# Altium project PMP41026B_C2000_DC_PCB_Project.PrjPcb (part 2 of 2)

## Sheet PMP41026B_C2000_DC_LLC_Control.SchDoc
size 558 x 431 mm; Date: Not shown in title block; ApprovedBy: Not shown in title block; CheckedBy: Not shown in title block; Author: Not shown in title block; CompanyName: Not shown in title block; DrawnBy: Desheng Guo; Engineer: Not shown in title block; Organization: Not shown in title block; Address1: Not shown in title block; Address2: Not shown in title block; Address3: Not shown in title block; Address4: Not shown in title block; DocumentNumber: 1; Revision: Use project parameter SCH_Rev; SheetNumber: 4; SheetTotal: 5; PageSetup: Record=PageOptions¦CenterHorizontal=True¦CenterVertical=True¦PrintScale=0.69¦XCorrection=1.00¦YCorrection=1.00¦PrintKind=0¦BorderSize=5000000¦LeftOffset=0¦BottomOffset=0¦Orientation=2¦PaperLength=1000¦PaperWidth=1000¦Scale=100¦PaperSource=15¦PrintQuality=600¦MediaType=1¦DitherType=10¦PaperKind=Letter¦PrintScaleMode=1
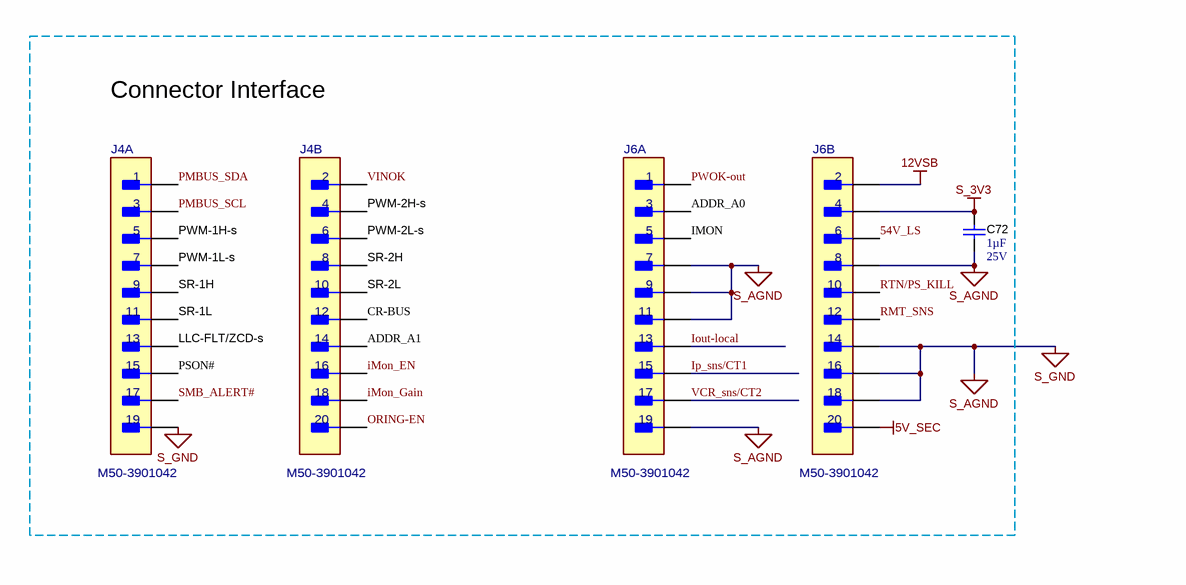
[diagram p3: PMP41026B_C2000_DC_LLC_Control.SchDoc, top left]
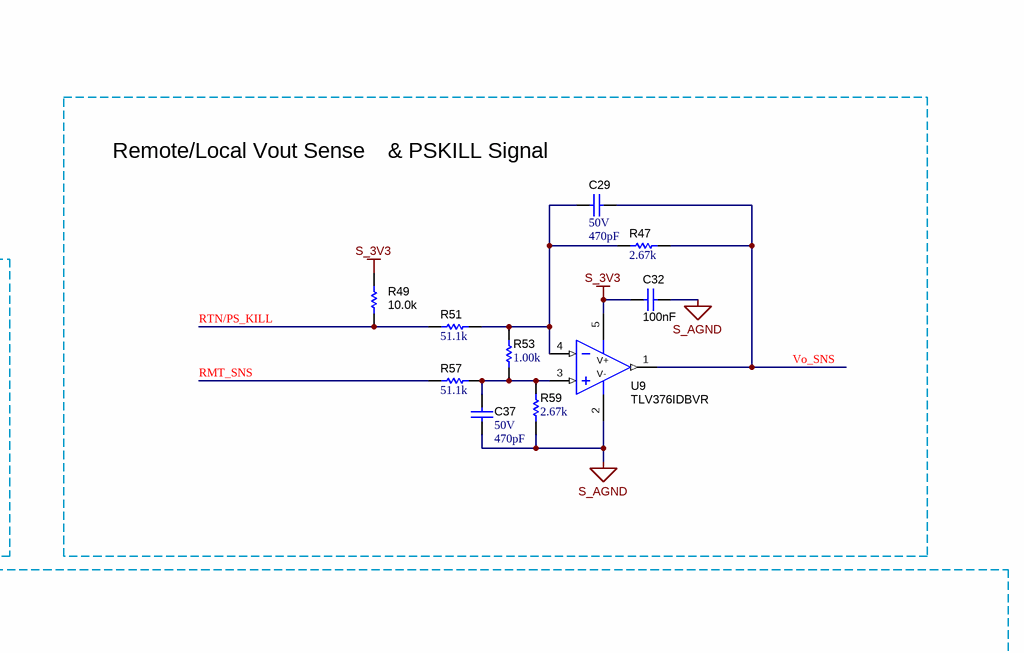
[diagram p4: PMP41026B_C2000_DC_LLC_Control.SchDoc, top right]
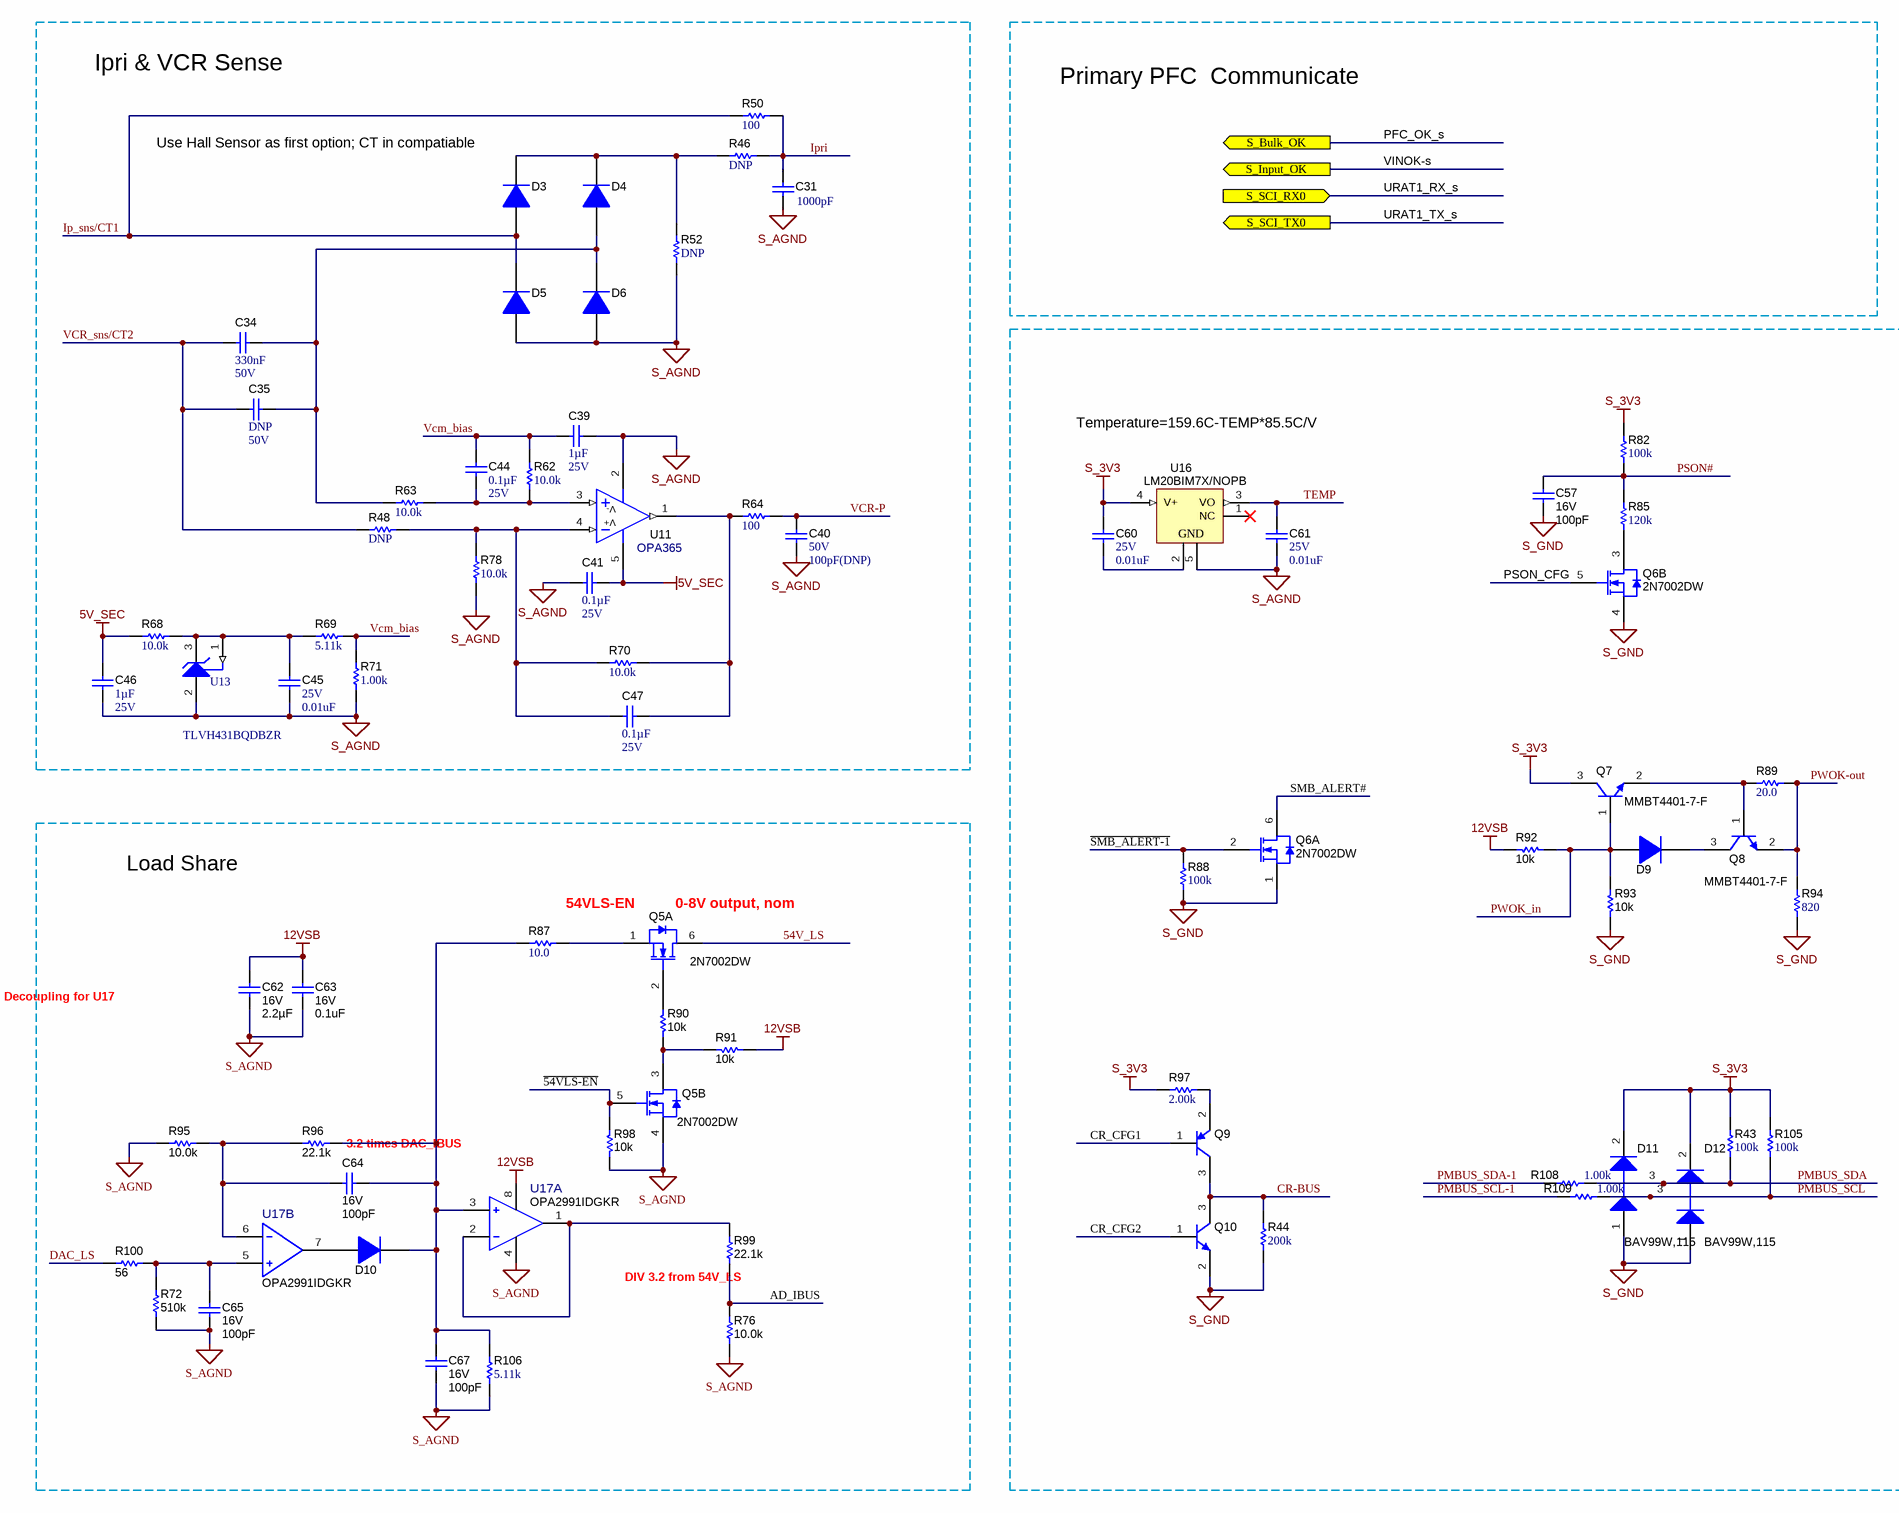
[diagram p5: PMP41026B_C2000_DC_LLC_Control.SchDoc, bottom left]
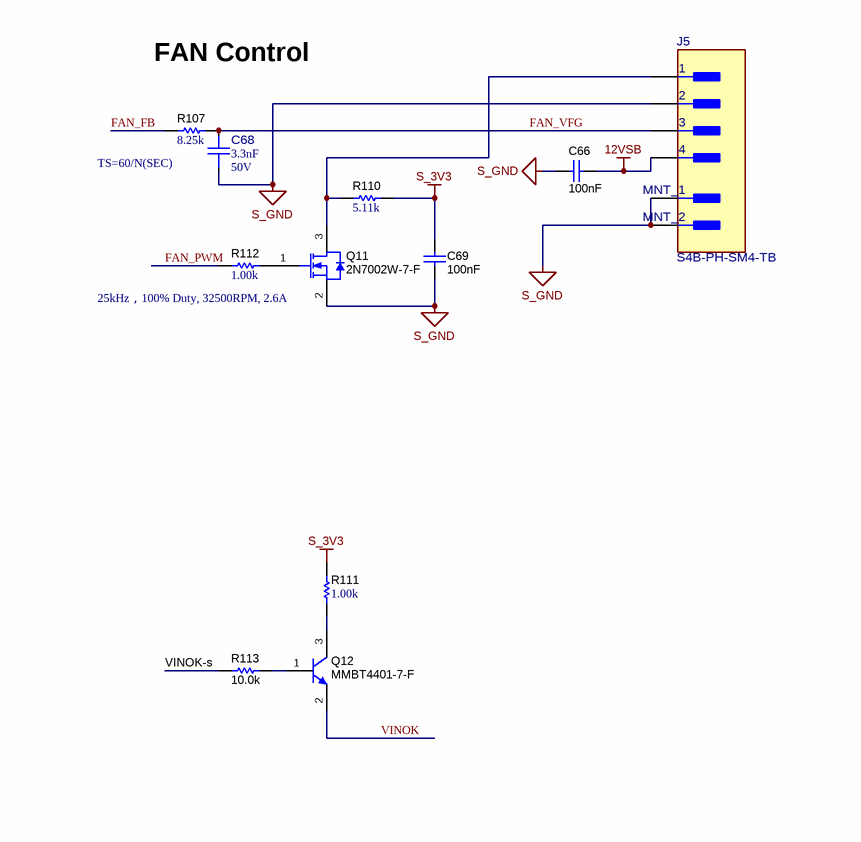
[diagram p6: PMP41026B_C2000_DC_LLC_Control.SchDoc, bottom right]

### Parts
C29  VDC_V: 50V  ValueDisplayed: 470pF  [0402]  (hidden comment: GRM155R71H471KA01D)
C31  ValueDisplayed: 1000pF  [0402]  (hidden comment: GRM155R72A102KA01D)
C32  Cap_F: 100nF  [0603]  (hidden comment: GRM188R71E104KA01D)
C34  Cap_F: 330nF  VDC_V: 50V  [0603]  (hidden comment: C1608X7R1H334K080AC)
C35  Cap_F: DNP  VDC_V: 50V  [0603]  (hidden comment: C1608X7R1H334K080AC)  (no BOM)
C37  VDC_V: 50V  ValueDisplayed: 470pF  [0402]  (hidden comment: GRM155R71H471KA01D)
C39  Cap_F: 1µF  VDC_V: 25V  [0603]  (hidden comment: 885012206076)
C40  VDC_V: 50V  ValueDisplayed: 100pF(DNP)  [0402]  (hidden comment: CC0402KRX7R9BB101)  (no BOM)
C41  ValueDisplayed: 0.1µF  VDC_V: 25V  [0402]  (hidden comment: CC0402KRX7R8BB104)
C44  ValueDisplayed: 0.1µF  VDC_V: 25V  [0402]  (hidden comment: CC0402KRX7R8BB104)
C45  VDC_V: 25V  ValueDisplayed: 0.01uF  [0402]  (hidden comment: GRM155R71E103KA01D)
C46  Cap_F: 1µF  VDC_V: 25V  [0603]  (hidden comment: 885012206076)
C47  ValueDisplayed: 0.1µF  VDC_V: 25V  [0402]  (hidden comment: CC0402KRX7R8BB104)
C57  VDC_V: 16V  ValueDisplayed: 100pF  [0402]  (hidden comment: 0402YC101KAT2A)
C60  VDC_V: 25V  ValueDisplayed: 0.01uF  [0402]  (hidden comment: GCM155R71E103KA37D)
C61  VDC_V: 25V  ValueDisplayed: 0.01uF  [0402]  (hidden comment: GCM155R71E103KA37D)
C62  VDC_V: 16V  Cap_F: 2.2µF  [0603]  (hidden comment: GRM188Z71C225KE43)
C63  VDC_V: 16V  ValueDisplayed: 0.1uF  [0402]  (hidden comment: GRM155R71C104KA88D)
C64  VDC_V: 16V  ValueDisplayed: 100pF  [0402]  (hidden comment: 0402YC101KAT2A)
C65  VDC_V: 16V  ValueDisplayed: 100pF  [0402]  (hidden comment: 0402YC101KAT2A)
C66  Cap_F: 100nF  [0603]  (hidden comment: GRM188R71E104KA01D)
C67  VDC_V: 16V  ValueDisplayed: 100pF  [0402]  (hidden comment: 0402YC101KAT2A)
C68  ValueDisplayed: 3.3nF  VDC_V: 50V  [FP-885012205064_0402-MFG]  (hidden comment: 885012205064)
C69  Cap_F: 100nF  [0603]  (hidden comment: GRM188R71E104KA01D)
C72  Cap_F: 1µF  VDC_V: 25V  [0603]  (hidden comment: 885012206076)
D3  BAS316,115  [SOD-323]  (value not drawn)
D4  BAS316,115  [SOD-323]  (value not drawn)
D5  BAS316,115  [SOD-323]  (value not drawn)
D6  BAS316,115  [SOD-323]  (value not drawn)
D9  BAS516,115  [SOD-523]  (value not drawn)
D10  BAS516,115  [SOD-523]  (value not drawn)
D11  BAV99W,115  [SOT-323]
D12  BAV99W,115  [SOT-323]
J4  M50-3901042  [FP-M50-3901042_HDR20-MFG]  (parts A,B of 2)
J5  S4B-PH-SM4-TB  [FP-S4B-PH-SM4-TB_CONN_HDR4-MFG]
J6  M50-3901042  [FP-M50-3901042_HDR20-MFG]  (parts A,B of 2)
Q5  2N7002DW  [SOT-363]  (parts A,B of 2)
Q6  2N7002DW  [SOT-363]  (parts A,B of 2)
Q7  MMBT4401-7-F  [SOT-23]
Q8  MMBT4401-7-F  [SOT-23]
Q9  MMBT4403  [SOT-23]  (value not drawn)
Q10  MMBT4401-7-F  [SOT-23]  (value not drawn)
Q11  2N7002W-7-F  [SOT-323]
Q12  MMBT4401-7-F  [SOT-23]
R43  ValueDisplayed: 100k  [0402]  (hidden comment: RC1005F104CS)
R44  ValueDisplayed: 200k  [0402]  (hidden comment: ERJ-2RKF2003X)
R46  ValueDisplayed: DNP  [0402]  (hidden comment: RC0402FR-07100RL)  (no BOM)
R47  ValueDisplayed: 2.67k  [0402]  (hidden comment: CRCW04022K67FKED)
R48  ValueDisplayed: DNP  [0402]  (hidden comment: CRCW040210K0FKED)  (no BOM)
R49  ValueDisplayed: 10.0k  [0402]  (hidden comment: CRCW040210K0FKED)
R50  ValueDisplayed: 100  [0402]  (hidden comment: RC0402FR-07100RL)
R51  ValueDisplayed: 51.1k  [0402]  (hidden comment: CRCW040251K1FKED)
R52  ValueDisplayed: DNP  [0805_HV]  (hidden comment: RC0805JR-072R2L)  (no BOM)
R53  ValueDisplayed: 1.00k  [0402]  (hidden comment: ERJ-2RKF1001X)
R57  ValueDisplayed: 51.1k  [0402]  (hidden comment: CRCW040251K1FKED)
R59  ValueDisplayed: 2.67k  [0402]  (hidden comment: CRCW04022K67FKED)
R62  ValueDisplayed: 10.0k  [0402]  (hidden comment: CRCW040210K0FKED)
R63  ValueDisplayed: 10.0k  [0402]  (hidden comment: CRCW040210K0FKED)
R64  ValueDisplayed: 100  [0402]  (hidden comment: RC0402FR-07100RL)
R68  ValueDisplayed: 10.0k  [0402]  (hidden comment: CRCW040210K0FKED)
R69  ValueDisplayed: 5.11k  [0402]  (hidden comment: CRCW04025K11FKED)
R70  ValueDisplayed: 10.0k  [0402]  (hidden comment: CRCW040210K0FKED)
R71  ValueDisplayed: 1.00k  [0402]  (hidden comment: RC0402FR-071KL)
R72  ValueDisplayed: 510k  [0402]  (hidden comment: CRCW0402510KJNED)
R76  ValueDisplayed: 10.0k  [0402]  (hidden comment: CRCW040210K0FKED)
R78  ValueDisplayed: 10.0k  [0402]  (hidden comment: CRCW040210K0FKED)
R82  ValueDisplayed: 100k  [0402]  (hidden comment: RC1005F104CS)
R85  ValueDisplayed: 120k  [0402]  (hidden comment: ERJ-2RKF1203X)
R87  ValueDisplayed: 10.0  [0402]  (hidden comment: MCR01MZPF10R0)
R88  ValueDisplayed: 100k  [0402]  (hidden comment: RC1005F104CS)
R89  ValueDisplayed: 20.0  [0402]  (hidden comment: CRCW040220R0FKED)
R90  ValueDisplayed: 10k  [0402]  (hidden comment: CRCW040210K0JNED)
R91  ValueDisplayed: 10k  [0402]  (hidden comment: CRCW040210K0JNED)
R92  ValueDisplayed: 10k  [0402]  (hidden comment: CRCW040210K0JNED)
R93  ValueDisplayed: 10k  [0402]  (hidden comment: CRCW040210K0JNED)
R94  ValueDisplayed: 820  [0402]  (hidden comment: RC0402FR-07820RL)
R95  ValueDisplayed: 10.0k  [0402]  (hidden comment: CRCW040210K0FKED)
R96  ValueDisplayed: 22.1k  [0402]  (hidden comment: CRCW040222K1FKED)
R97  ValueDisplayed: 2.00k  [0402]  (hidden comment: CRCW04022K00FKED)
R98  ValueDisplayed: 10k  [0402]  (hidden comment: CRCW040210K0JNED)
R99  ValueDisplayed: 22.1k  [0402]  (hidden comment: CRCW040222K1FKED)
R100  ValueDisplayed: 56  [0402]  (hidden comment: CRCW040256R0JNED)
R105  ValueDisplayed: 100k  [0402]  (hidden comment: RC1005F104CS)
R106  ValueDisplayed: 5.11k  [0402]  (hidden comment: CRCW04025K11FKED)
R107  ValueDisplayed: 8.25k  [0402]  (hidden comment: CRCW04028K25FKED)
R108  ValueDisplayed: 1.00k  [0402]  (hidden comment: ERJ-2RKF1001X)
R109  ValueDisplayed: 1.00k  [0402]  (hidden comment: ERJ-2RKF1001X)
R110  ValueDisplayed: 5.11k  [0402]  (hidden comment: CRCW04025K11FKED)
R111  ValueDisplayed: 1.00k  [0402]  (hidden comment: RC0402FR-071KL)
R112  ValueDisplayed: 1.00k  [0402]  (hidden comment: ERJ-2RKF1001X)
R113  ValueDisplayed: 10.0k  [0402]  (hidden comment: CRCW040210K0FKED)
U9  TLV376IDBVR  [DBV0005A_N]
U11  OPA365  [DBV0005A_N]
U13  TLVH431BQDBZR  [DBZ0003A_N]
U16  LM20BIM7X/NOPB  [DCK0005A_N]
U17  OPA2991IDGKR  [DGK0008A-MFG]  (parts A,B of 2)

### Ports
S_Bulk_OK (out), S_Input_OK (out), S_SCI_RX0 (in), S_SCI_TX0 (out)

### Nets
5V_SEC: C41.1 C46.2 J6.20 R68.1 U11.5(V+)
12VSB: C62.1 C63.1 C66.1 J5.4 J6.2 R91.2 R92.1 U17.8(v+)
S_3V3: C32.2 C60.1 C69.2 C72.2 D11.2(K) D12.2(K) J6.4 Q7.3(C) R43.2 R49.1 R82.2 R97.2 R105.2 R110.1 R111.2 U9.5(V+) U16.4(V+)
S_AGND: C31.2 C32.1 C37.2 C39.2 C40.2 C41.2 C45.2 C46.1 C57.2 C61.2 C62.2 C63.2 C65.2 C66.2 C67.2 C68.1 C69.1 C72.1 D5.2(A) D6.2(A) D11.1(A) D12.1(A) J4.19 J5.2 J5.5(MNT_1) J5.6(MNT_2) J6.7 J6.8 J6.9 J6.11 J6.14 J6.16 J6.18 J6.19 Q5.4(S) Q6.1(S) Q6.4(S) Q10.2(E) Q11.2(S) R44.1 R52.1 R59.1 R71.1 R72.1 R76.1 R78.1 R88.1 R93.1 R94.1 R95.2 R98.2 R106.1 U9.2(V-) U11.2(V-) U13.2(CATHODE) U16.5(GND) U17.4(V-)  [also labelled S_GND]
54V_LS: J6.6 Q5.6(D)
~{54VLS-EN}: Q5.5(G) R98.1
~{SMB_ALERT-1}: Q6.2(G) R88.2
AD_IBUS: R76.2 R99.1
ADDR_A0: J6.3
ADDR_A1: J4.14
CR-BUS: J4.12 Q9.3(C) Q10.3(C) R44.2
CR_CFG1: Q9.1(B)
CR_CFG2: Q10.1(B)
DAC_LS: R100.1
FAN_FB: R107.1
FAN_PWM: R112.2
FAN_VFG: C68.2 J5.3 R107.2
IMON: J6.5
iMon_EN: J4.16
iMon_Gain: J4.18
Iout-local: J6.13
Ip_sns/CT1: D3.2(A) D5.1(K) J6.15 R50.1
Ipri: C31.1 R46.2 R50.2
LLC-FLT/ZCD-s: J4.13
ORING-EN: J4.20
PMBUS_SCL: D12.3(C) J4.3 R105.1 R109.2
PMBUS_SCL-1: R109.1  [project net MCU_GPIO24]
PMBUS_SDA: D11.3(C) J4.1 R43.1 R108.2
PMBUS_SDA-1: R108.1
PSON#: C57.1 J4.15 R82.1 R85.2
PSON_CFG: Q6.5(G)
PWM-1H-s: J4.5
PWM-1L-s: J4.7
PWM-2H-s: J4.4
PWM-2L-s: J4.6
PWOK-out: J6.1 Q8.2(E) R89.2 R94.2
PWOK_in: D9.2(A) Q7.1(B) R92.2 R93.2
RMT_SNS: J6.12 R57.1
RTN/PS_KILL: J6.10 R49.2 R51.1
SMB_ALERT#: J4.17 Q6.6(D)
SR-1H: J4.9
SR-1L: J4.11
SR-2H: J4.8
SR-2L: J4.10
TEMP: C61.1 U16.3(VO)
Vcm_bias: C39.1 C44.1 R62.2 R69.1 R71.2
VCR-P: C40.1 R64.2
VCR_sns/CT2: C34.2 C35.2 J6.17 R48.1
VINOK: J4.2 Q12.2(E)
VINOK-s: R113.1 ; port S_Input_OK
Vo_SNS: C29.2 R47.2 U9.1(OUT)
NetC29_1: C29.1 R47.1 R51.2 R53.2 U9.4(IN-)
NetC34_1: C34.1 C35.1 D4.2(A) D6.1(K) R63.1
NetC37_1: C37.1 R53.1 R57.2 R59.2 U9.3(IN+)
NetC44_2: C44.2 R62.1 R63.2 U11.3(IN+)
NetC45_1: C45.1 R68.2 R69.2 U13.1(REF) U13.3(ANODE)
NetC47_1: C47.1 R64.1 R70.2 U11.1(OUT)
NetC47_2: C47.2 R48.2 R70.1 R78.2 U11.4(IN-)
NetC60_2: C60.2 U16.2(GND)
NetC64_1: C64.1 R95.1 R96.1 U17.6(IN2-)
NetC64_2: C64.2 C67.1 D10.1(K) R87.1 R96.2 R106.2 U17.3(IN1+)
NetC65_1: C65.1 R72.2 R100.2 U17.5(IN2+)
NetD3_1: D3.1(K) D4.1(K) R46.1 R52.2
NetD9_1: D9.1(K) Q8.3(C)
NetD10_2: D10.2(A) U17.7(OUT2)
NetJ5_1: J5.1 Q11.3(D) R110.2
NetQ5_1: Q5.1(S) R87.2
NetQ5_2: Q5.2(G) R90.1
NetQ5_3: Q5.3(D) R90.2 R91.1
NetQ6_3: Q6.3(D) R85.1
NetQ7_2: Q7.2(E) Q8.1(B) R89.1
NetQ9_2: Q9.2(E) R97.1
NetQ11_1: Q11.1(G) R112.1
NetQ12_1: Q12.1(B) R113.2
NetQ12_3: Q12.3(C) R111.1
NetR99_2: R99.2 U17.1(OUT1) U17.2(IN1-)

Not connected (* = marked no-connect by the designer): U16 1(NC)*

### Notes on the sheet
- Connector Interface
- Remote/Local Vout Sense
- & PSKILL Signal
- Ipri & VCR Sense
- Primary PFC  Communicate
- (near D3) Use Hall Sensor as first option; CT in compatiable
- Temperature=159.6C-TEMP*85.5C/V
- FAN Control
- (near R107) TS=60/N(SEC)
- 25kHz，100% Duty, 32500RPM, 2.6A
- Load Share
- (near Q5) 54VLS-EN
- 0-8V output, nom
- (near C62) Decoupling for U17
- 3.2 times DAC_IBUS
- (near R99) DIV 3.2 from 54V_LS

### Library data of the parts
C29 C37 = CMP-0006691-2: CAP, CERM, 470 pF, 50 V, +/- 10%, X7R, 0402; Manufacturer: MuRata; TaMin_C: -55°C; Polarized: N; SizeAreaWB_mm2: 3; Value1: Unknown; U/M: EA; Value: 470pF; TaMax_C: 125°C; SizeZ_mm: 0.6; SizeX_mm: 1; SizeY_mm: 0.5; AEC Category: Q200
C31 = CMP-0006699-2: CAP, CERM, 1000 pF, 100 V, +/- 10%, X7R, 0402; Manufacturer: MuRata; TaMin_C: -55°C; Polarized: N; SizeAreaWB_mm2: 3; Value1: Unknown; U/M: EA; Value: 1000pF; TaMax_C: 125°C; SizeZ_mm: 0.6; SizeX_mm: 1; SizeY_mm: 0.5; Value2: 100V; Cap_F: 1nF; AEC Category: Q200
C32 C66 C69 = CMP-0007404-4: CAP, CERM, 0.1 uF, 25 V, +/- 10%, X7R, 0603; Manufacturer: MuRata; TaMin_C: -55°C; Polarized: N; SizeAreaWB_mm2: 4.68; Value1: Unknown; U/M: EA; Value: 0.1uF; TaMax_C: 125°C; SizeZ_mm: 1; SizeX_mm: 1.6; SizeY_mm: 0.8; Value2: 25V; SizeArea_mm2: 1.28; CompType: Capacitor; AEC Category: Q200
C34 C35 = CMP-0007048-4: CAP, CERM, 0.33 uF, 50 V, +/- 10%, X7R, 0603; Manufacturer: TDK; TaMin_C: -55°C; ESR_ohm: 0.016574; Polarized: N; SizeAreaWB_mm2: 4.68; Value1: 0.016574 ohm; U/M: EA; Value: 0.33uF; TaMax_C: 125°C; SizeZ_mm: 1; SizeX_mm: 1.6; SizeY_mm: 0.8; SizeArea_mm2: 1.28; IRMS_A: 1.28367A; AEC Category: Q200
C39 C46 C72 = CMP-0006833-4: CAP, CERM, 1 uF, 25 V, +/- 10%, X7R, 0603; Manufacturer: Wurth Elektronik; TaMin_C: -55°C; Polarized: N; SizeAreaWB_mm2: 4.68; Value1: Unknown; U/M: EA; Value: 1uF; TaMax_C: 125°C; SizeZ_mm: 1; SizeX_mm: 1.6; SizeY_mm: 0.8; SizeArea_mm2: 1.28; AEC Category: Q200
C40 = CMP-0006305-2: CAP, CERM, 100 pF, 50 V, +/- 10%, X7R, 0402; Manufacturer: Yageo America; TaMin_C: -55°C; Polarized: N; SizeAreaWB_mm2: 3; Value1: Unknown; U/M: EA; Value: 100pF; TaMax_C: 125°C; SizeZ_mm: 0.6; SizeX_mm: 1; SizeY_mm: 0.5; AEC Category: Q200
C41 C44 C47 = CMP-0860555-1: CAP, CERM, 0.1 µF, 25 V,+/- 10%, X7R, 0402; Manufacturer: Yageo; SizeArea_mm2: 0.5; AEC Qualified: N; SizeX_mm: 1; U/M: EA; Value: 0.1uF; TaMin_C: -55°C; SizeZ_mm: 0.6; Cap_F: 100nF; TaMax_C: 125°C; SizeAreaWB_mm2: 3; AEC Category: Q200
C45 = CMP-0006658-2: CAP, CERM, 0.01 uF, 25 V, +/- 10%, X7R, 0402; Manufacturer: MuRata; TaMin_C: -55°C; Polarized: N; SizeAreaWB_mm2: 3; Value1: Unknown; U/M: EA; Value: 0.01uF; TaMax_C: 125°C; SizeZ_mm: 0.6; SizeX_mm: 1; SizeY_mm: 0.5; Cap_F: 10nF; AEC Category: Q200
C57 C64 C65 C67 = CMP-0006200-2: CAP, CERM, 100 pF, 16 V, +/- 10%, X7R, 0402; Manufacturer: AVX; TaMin_C: -55°C; Polarized: N; SizeAreaWB_mm2: 3; Value1: Unknown; U/M: EA; Value: 100pF; TaMax_C: 125°C; SizeZ_mm: 0.6; SizeX_mm: 1; SizeY_mm: 0.5; AEC Category: Q200
C60 C61 = CMP-0006352-2: CAP, CERM, 0.01 uF, 25 V, +/- 10%, X7R, 0402; Manufacturer: MuRata; TaMin_C: -55°C; Polarized: N; SizeAreaWB_mm2: 3; Value1: Unknown; U/M: EA; Value: 0.01uF; TaMax_C: 125°C; SizeZ_mm: 0.6; SizeX_mm: 1; SizeY_mm: 0.5; Cap_F: 10nF; AEC Category: Q200
C62 = CMP-0007499-4: CAP, CERM, 2.2 uF, 16 V, +/- 10%, X7R, 0603; Manufacturer: MuRata; TaMin_C: -55°C; Polarized: N; SizeAreaWB_mm2: 4.68; Value1: Unknown; U/M: EA; Value: 2.2uF; TaMax_C: 125°C; SizeZ_mm: 1; SizeX_mm: 1.6; SizeY_mm: 0.8; SizeArea_mm2: 1.28; AEC Category: Q200
C63 = CMP-0006641-2: CAP, CERM, 0.1 uF, 16 V, +/- 10%, X7R, 0402; Manufacturer: MuRata; TaMin_C: -55°C; Polarized: N; SizeAreaWB_mm2: 3; Value1: Unknown; U/M: EA; Value: 0.1uF; TaMax_C: 125°C; SizeZ_mm: 0.6; SizeX_mm: 1; SizeY_mm: 0.5; Cap_F: 100nF; AEC Category: Q200
C68 = CMP-0092424-1: Cap Cer 3300pF 50V X7R 0402; Manufacturer: Wurth Electronics; TempCo: 15%; AEC Qualified: No; Value: 3.3nF; SizeZ_mm: 0.55mm; Tolerance_%: 10%
D3-D6 = CMP-0029006-1: Diode, Ultrafast, 100 V, 0.25 A, SOD-323; Manufacturer: Nexperia; Io_A: 250mA; Green_Lifecycle: Not Set; SizeAreaWB_mm2: 8.695; Vr_V: 100V; Green_REACh: Incomplete; Value1: 0.25A; TJmax_C: 150°C; U/M: EA; Value: 100V; SizeZ_mm: 1; SizeX_mm: 2.7; SizeY_mm: 1.35; Vf_V: 1.4V; SizeArea_mm2: 3.645; AEC Category: Q101
D9 D10 = CMP-0076979-3: Diode, Switching, 100 V, 0.25 A, SOD-523; Manufacturer: Nexperia; Value: 100V; SizeAreaWB_mm2: 5.13; Vf_V: 1.25V; SizeArea_mm2: 1.53; SizeY_mm: 0.9; Green_Lifecycle: Not Set; AEC Category: Q101; SizeX_mm: 1.7; Green_REACh: Incomplete; Io_A: 250mA; TJmax_C: 150°C; SizeZ_mm: 0.65; Value1: 0.25A
D11 D12 = CMP-0076926-2: Diode, Switching, 100 V, 0.15 A, SOT-323; Manufacturer: Nexperia; AEC Category: Q101; SizeAreaWB_mm2: 10.24; TJmax_C: 150°C; Green_REACh: Incomplete; SizeArea_mm2: 4.84; Value: 100V; Vf_V: 1.25V; Green_Lifecycle: Not Set; SizeZ_mm: 1.1; Value1: 0.15A; Io_A: 150mA; SizeY_mm: 2.2
J4 J6 = CMP-0122579-1: Connector Header Through Hole, Right Angle 20 position 0.050" (1.27mm); Manufacturer: Harwin; ContactFinish: Gold,Nickel; Current_A: 1A; Row_Count: 2; AEC Qualified: No; Conn Gender: Male; Conn Orientation: Horizontal; SizeZ_mm: 3.55mm
J5 = CMP-0123064-1: Connector Header, PH Series, 4 Position, Side Entry, 2.00mm, Solder, Surface Mount, Natural.; Manufacturer: JST; ContactFinish: Tin,Copper; Current_A: 2A; Row_Count: 1; Voltage_V: 100V; AEC Qualified: No; DUT-Pitch_mm: 2mm; SizeZ_mm: 5.5mm
Q5 Q6 = CMP-0000770-1: MOSFET, 2-CH, N-CH, 60 V, 0.115 A, SOT-363; Alternate Manufacturer: None; Manufacturer: Fairchild Semiconductor; SizeZ_mm: 1.1; ChType: N; VdsMax_V: 60V; SizeX_mm: 2.2; Vgs_V: 20V; Value: 60V; SizeArea_mm2: 4.84; AEC Category: Q101; IdsMax_A: 1.15dA; SizeAreaWB_mm2: 10.24; U/M: EA
Q7 Q8 Q10 Q12 = CMP-0000388-2: Transistor, NPN, 40 V, 0.15 A, SOT-23; Manufacturer: Diodes Inc.; TaMax_C: 150°C; Value2: 300; Value1: 0.15 A; Vcesat1_V: 4dV; SizeX_mm: 2.5; SizeY_mm: 3; TaMin_C: -55°C; IcRated_A: 1.5dA; CompType: BJT; SizeZ_mm: 1.1; Value: 40 V; SizeArea_mm2: 7.5; NPN: 1; Vceo_V: 40V; PNP: 0; AEC Category: Q101; SizeAreaWB_mm2: 14; U/M: EA
Q9 = CMP-0000327-2: Transistor, PNP, 40 V, 0.6 A, SOT-23; Manufacturer: Fairchild Semiconductor; TaMax_C: 150°C; Value2: 500; Value1: 0.6 A; Vcesat1_V: 7.5dV; SizeX_mm: 2.5; SizeY_mm: 3; TaMin_C: -55°C; IcRated_A: 6dA; CompType: BJT; SizeZ_mm: 1.1; Value: 40 V; SizeArea_mm2: 7.5; NPN: 0; Vceo_V: 40V; PNP: 1; AEC Category: Q101; SizeAreaWB_mm2: 14; U/M: EA
Q11 = CMP-0000776-1: MOSFET, N-CH, 60 V, 0.115 A, SOT-323; Alternate Manufacturer: None; Manufacturer: Diodes Inc.; SizeZ_mm: 1.1; ChType: N; Value1: 7; VdsMax_V: 60V; SizeX_mm: 2.2; Vgs_V: 20V; Value: 60V; Rdson45_ohm: 7.5; SizeArea_mm2: 4.84; AEC Category: Q101; IdsMax_A: 1.15dA; SizeAreaWB_mm2: 10.24; U/M: EA
R43 R82 R88 R105 = CMP-0026745-1: RES, 100 k, 1%, 0.063 W, 0402; Manufacturer: Samsung Electro-Mechanics; Power_W: 63mW; TempCo: 100 ppm/C; U/M: EA; Value: 100k; EIA_Code: E96; SizeX_mm: 1; SizeY_mm: 0.5; SizeZ_mm: 0.6; Value2: 0.063W; AEC Qualified: N; VDC_V: 80V; AEC Category: Q200
R44 = CMP-0026677-1: RES, 200 k, 1%, 0.1 W, 0402; Manufacturer: Panasonic; Power_W: 100mW; TempCo: 100 ppm/C; U/M: EA; Value: 200k; EIA_Code: E96; SizeX_mm: 1; SizeY_mm: 0.5; SizeZ_mm: 0.6; Value2: 0.1W; VDC_V: 50V; AEC Category: Q200
R46 R50 R64 = CMP-0026722-1: RES, 100, 1%, 0.063 W, 0402; Manufacturer: Yageo America; Power_W: 63mW; TempCo: 100 ppm/C; Value_Code: 100R; U/M: EA; Value: 100; EIA_Code: E96; SizeX_mm: 1; SizeY_mm: 0.5; SizeZ_mm: 0.6; Value2: 0.063W; AEC Qualified: N; VDC_V: 50V; AEC Category: Q200
R47 R59 = CMP-0026240-2: RES, 2.67 k, 1%, 0.063 W, AEC-Q200 Grade 0, 0402; Manufacturer: Vishay-Dale; Power_W: 63mW; TempCo: 100 ppm/C; Value_Code: 2k67; Value: 2.67k; EIA_Code: E96; SizeX_mm: 1; SizeY_mm: 0.5; SizeZ_mm: 0.6; Value2: 0.063W; AEC Qualified: Y; VDC_V: 50V; AEC Category: Q200; AEC Grade: 0
R48 R49 R62 R63 R68 R70 R76 R78 R95 R113 = CMP-0025958-3: RES, 10.0 k, 1%, 0.063 W, AEC-Q200 Grade 0, 0402; Manufacturer: Vishay-Dale; Power_W: 63mW; TempCo: 100 ppm/C; Value_Code: 10k0; Value: 10.0k; EIA_Code: E96; Res_ohm: 10k; SizeX_mm: 1; SizeY_mm: 0.5; SizeZ_mm: 0.6; Value2: 0.063W; AEC Qualified: Y; VDC_V: 50V; AEC Category: Q200; AEC Grade: 0
R51 R57 = CMP-0026437-2: RES, 51.1 k, 1%, 0.063 W, AEC-Q200 Grade 0, 0402; Manufacturer: Vishay-Dale; Power_W: 63mW; TempCo: 100 ppm/C; Value_Code: 51k1; Value: 51.1k; EIA_Code: E96; SizeX_mm: 1; SizeY_mm: 0.5; SizeZ_mm: 0.6; Value2: 0.063W; AEC Qualified: Y; VDC_V: 50V; AEC Category: Q200; AEC Grade: 0
R52 = CMP-0020812-2: RES, 2.2, 5%, 0.125 W, 0805; Manufacturer: Yageo America; Power_W: 125mW; TempCo: 200 ppm/C; Value_Code: 2R20; U/M: EA; Value: 2.2; EIA_Code: E24; SizeX_mm: 2; SizeY_mm: 1.25; SizeZ_mm: 1.45; Value2: 0.125W; SizeArea_mm2: 2.5; VDC_V: 150V; AEC Category: Q200
R53 R108 R109 R112 = CMP-0026657-1: RES, 1.00 k, 1%, 0.1 W, 0402; Manufacturer: Panasonic; Power_W: 100mW; TempCo: 100 ppm/C; Value_Code: 1k00; U/M: EA; Value: 1.00k; EIA_Code: E96; Res_ohm: 1k; SizeX_mm: 1; SizeY_mm: 0.5; SizeZ_mm: 0.6; Value2: 0.1W; VDC_V: 50V; AEC Category: Q200
R69 R106 R110 = CMP-0026463-2: RES, 5.11 k, 1%, 0.063 W, AEC-Q200 Grade 0, 0402; Manufacturer: Vishay-Dale; Power_W: 63mW; TempCo: 100 ppm/C; Value_Code: 5k11; Value: 5.11k; EIA_Code: E96; SizeX_mm: 1; SizeY_mm: 0.5; SizeZ_mm: 0.6; Value2: 0.063W; AEC Qualified: Y; VDC_V: 50V; AEC Category: Q200; AEC Grade: 0
R71 R111 = CMP-0026725-1: RES, 1.00 k, 1%, 0.0625 W, 0402; Manufacturer: Yageo America; Power_W: 62.5mW; TempCo: 100 ppm/C; Value_Code: 1k00; U/M: EA; Value: 1.00k; EIA_Code: E96; Res_ohm: 1k; SizeX_mm: 1; SizeY_mm: 0.5; SizeZ_mm: 0.6; AEC Qualified: N; VDC_V: 50V; AEC Category: Q200
R72 = CMP-0026943-2: RES, 510 k, 5%, 0.063 W, AEC-Q200 Grade 0, 0402; Manufacturer: Vishay-Dale; Power_W: 63mW; TempCo: 200 ppm/C; Value: 510k; EIA_Code: E24; SizeX_mm: 1; SizeY_mm: 0.5; SizeZ_mm: 0.6; Value2: 0.063W; AEC Qualified: Y; VDC_V: 50V; AEC Category: Q200; AEC Grade: 0
R85 = CMP-0026663-1: RES, 120 k, 1%, 0.1 W, AEC-Q200 Grade 0, 0402; Manufacturer: Panasonic; Power_W: 100mW; TempCo: 100 ppm/C; U/M: EA; Value: 120k; SizeX_mm: 1; SizeY_mm: 0.5; SizeZ_mm: 0.6; Value2: 0.1W; AEC Qualified: Y; VDC_V: 50V; AEC Grade: 0; AEC Category: Q200
R87 = CMP-0026717-1: RES, 10.0, 1%, 0.063 W, 0402; Manufacturer: Rohm; Power_W: 63mW; TempCo: 100 ppm/C; Value_Code: 10R0; U/M: EA; Value: 10.0; EIA_Code: E96; Res_ohm: 10; SizeX_mm: 1; SizeY_mm: 0.5; SizeZ_mm: 0.6; Value2: 0.063W; AEC Qualified: N; VDC_V: 50V; AEC Category: Q200
R89 = CMP-0026164-2: RES, 20.0, 1%, 0.063 W, AEC-Q200 Grade 0, 0402; Manufacturer: Vishay-Dale; Power_W: 63mW; TempCo: 100 ppm/C; Value_Code: 20R0; Value: 20.0; EIA_Code: E96; Res_ohm: 20; SizeX_mm: 1; SizeY_mm: 0.5; SizeZ_mm: 0.6; Value2: 0.063W; AEC Qualified: Y; VDC_V: 50V; AEC Category: Q200; AEC Grade: 0
R90-R93 R98 = CMP-0026825-5: RES, 10 k, 5%, 0.063 W, AEC-Q200 Grade 0, 0402; Manufacturer: Vishay-Dale; Value: 10k; Value_Code: 10k0; Power_W: 63mW; Value2: 0.063W; VDC_V: 50V; TempCo: 200 ppm/C; EIA_Code: E24; AEC Category: Q200; AEC Qualified: Y; AEC Grade: 0; SizeArea_mm2: 0.5; SizeX_mm: 1; SizeZ_mm: 0.6
R94 = CMP-0026743-1: RES, 820, 1%, 0.063 W, 0402; Manufacturer: Yageo America; Power_W: 63mW; TempCo: 100 ppm/C; Value_Code: 820R; U/M: EA; Value: 820; SizeX_mm: 1; SizeY_mm: 0.5; SizeZ_mm: 0.6; Value2: 0.063W; AEC Qualified: N; VDC_V: 50V; AEC Category: Q200
R96 R99 = CMP-0026178-2: RES, 22.1 k, 1%, 0.063 W, AEC-Q200 Grade 0, 0402; Manufacturer: Vishay-Dale; Power_W: 63mW; TempCo: 100 ppm/C; Value_Code: 22k1; Value: 22.1k; EIA_Code: E96; SizeX_mm: 1; SizeY_mm: 0.5; SizeZ_mm: 0.6; Value2: 0.063W; AEC Qualified: Y; VDC_V: 50V; AEC Category: Q200; AEC Grade: 0
R97 = CMP-0026227-2: RES, 2.00 k, 1%, 0.063 W, AEC-Q200 Grade 0, 0402; Manufacturer: Vishay-Dale; Power_W: 63mW; TempCo: 100 ppm/C; Value_Code: 2k00; Value: 2.00k; EIA_Code: E96; Res_ohm: 2k; SizeX_mm: 1; SizeY_mm: 0.5; SizeZ_mm: 0.6; Value2: 0.063W; AEC Qualified: Y; VDC_V: 50V; AEC Category: Q200; AEC Grade: 0
R100 = CMP-0026950-3: RES, 56, 5%, 0.063 W, AEC-Q200 Grade 0, 0402; Manufacturer: Vishay-Dale; Power_W: 63mW; TempCo: 200 ppm/C; Value_Code: 56R0; Value: 56; EIA_Code: E24; SizeX_mm: 1; SizeY_mm: 0.5; SizeZ_mm: 0.6; Value2: 0.063W; AEC Qualified: Y; VDC_V: 50V; AEC Category: Q200; AEC Grade: 0
R107 = CMP-0026589-2: RES, 8.25 k, 1%, 0.063 W, AEC-Q200 Grade 0, 0402; Manufacturer: Vishay-Dale; Power_W: 63mW; TempCo: 100 ppm/C; Value_Code: 8k25; Value: 8.25k; EIA_Code: E96; SizeX_mm: 1; SizeY_mm: 0.5; SizeZ_mm: 0.6; Value2: 0.063W; AEC Qualified: Y; VDC_V: 50V; AEC Category: Q200; AEC Grade: 0
U9 = CMP-0073542-1: TLVx376, 5.5 MHz, Low-Noise, Low Quiescent Current, Precision Operational Amplifiers, DBV0005A (SOT-23-5); Alternate PartNumber: TLV376IDBVT; Alternate Manufacturer: Texas Instruments; SizeAreaWB_mm2: 14.82; U/M: EA; SizeZ_mm: 1.45; SizeX_mm: 2.8; SizeY_mm: 2.9; SizeArea_mm2: 8.12; CompType: IC
U11 = CMP-0861047-2: 50-MHz, Low-Power, Gain of 6-V/V Stable, Rail-to-Rail Output CMOS Operational Amplifier, DBV0005A (SOT-23-5); Manufacturer: Texas Instruments; AEC Category: Q200; SizeY_mm: 2.9; SizeArea_mm2: 8.12; SizeX_mm: 2.8; SizeZ_mm: 1.45; SizeAreaWB_mm2: 14.82; AEC Qualified: N; CompType: IC
U13 = CMP-0033081-1: Low-Voltage Adjustable Precision Shunt Regulator, 80 mA, -40 to 125 degC, 3-pin SOT-23 (DBZ), Green (RoHS & no Sb/Br); Manufacturer: Texas Instruments; Min Iz for Regulation(uA): 80; Initial Accuracy @ 25/deg C(%): 0.5; VO Adj(Max)(V): 18; Rating: Catalog; SubFamily: Shunt Voltage Reference; Temp Coeff(Max)(ppm/ degree C): 129; VO Adj(Min)(V): 1.24
U16 = CMP-0073339-2: 2.4V, 10µA Temperature Sensor, 5-pin SC-70 Micro SMD, Pb-Free; Manufacturer: Texas Instruments; CompType: Temp Sensor IC; PackageTopMarking: T2B*XTT; PowerWise: N; AEC Category: Q200; SizeAreaWB_mm2: 9.3; SizeArea_mm2: 4.2; SizeX_mm: 2.1; SizeY_mm: 2.0; SizeZ_mm: 1.1
U17 = CMP-0092737-1: 40-V, dual-channel, 4.5-MHz, rail-to-rail input/output, low-offset-voltage, low-noise op amp 8-VSSOP -40 to 125; Manufacturer: Texas Instruments; Gain Bandwidth: 4.5MHz; SizeZ_mm: 1.1mm; Input Bias Current: 0.00001uA; Min Supply Voltage: 2.7V; Nominal Supply Current: 560uA; Max Supply Voltage: 40V; Number Of Channels: 2; Max Dual Supply Voltage: 20V; TJmax_C: +150°C; AEC Qualified: No; Output Current Per Channel: 75mA; Voltage Gain: 145dB; TaMax_C: +125°C; Min Dual Supply Voltage: 1.35V; TaMin_C: -40°C; Input Offset Voltage: 0.125mV; Standoff Height: 0.05mm; Response Time: 2.5us

## Sheet PMP41026B_C2000_DC_LLC_F280039C.SchDoc: F280039C for mCRPS D2D Stage
size A2; Date: Not shown in title block; ApprovedBy: Not shown in title block; CheckedBy: Not shown in title block; Author: Not shown in title block; CompanyName: Not shown in title block; DrawnBy: Desheng Guo; Engineer: Not shown in title block; Organization: Not shown in title block; Address1: Not shown in title block; Address2: Not shown in title block; Address3: Not shown in title block; Address4: Not shown in title block; DocumentNumber: 1; Revision: Use project parameter SCH_Rev; SheetNumber: 5; SheetTotal: 5; PageSetup: Record=PageOptions¦CenterHorizontal=True¦CenterVertical=True¦PrintScale=0.69¦XCorrection=1.00¦YCorrection=1.00¦PrintKind=0¦BorderSize=5000000¦LeftOffset=0¦BottomOffset=0¦Orientation=2¦PaperLength=1000¦PaperWidth=1000¦Scale=100¦PaperSource=15¦PrintQuality=600¦MediaType=1¦DitherType=10¦PaperKind=Letter¦PrintScaleMode=1
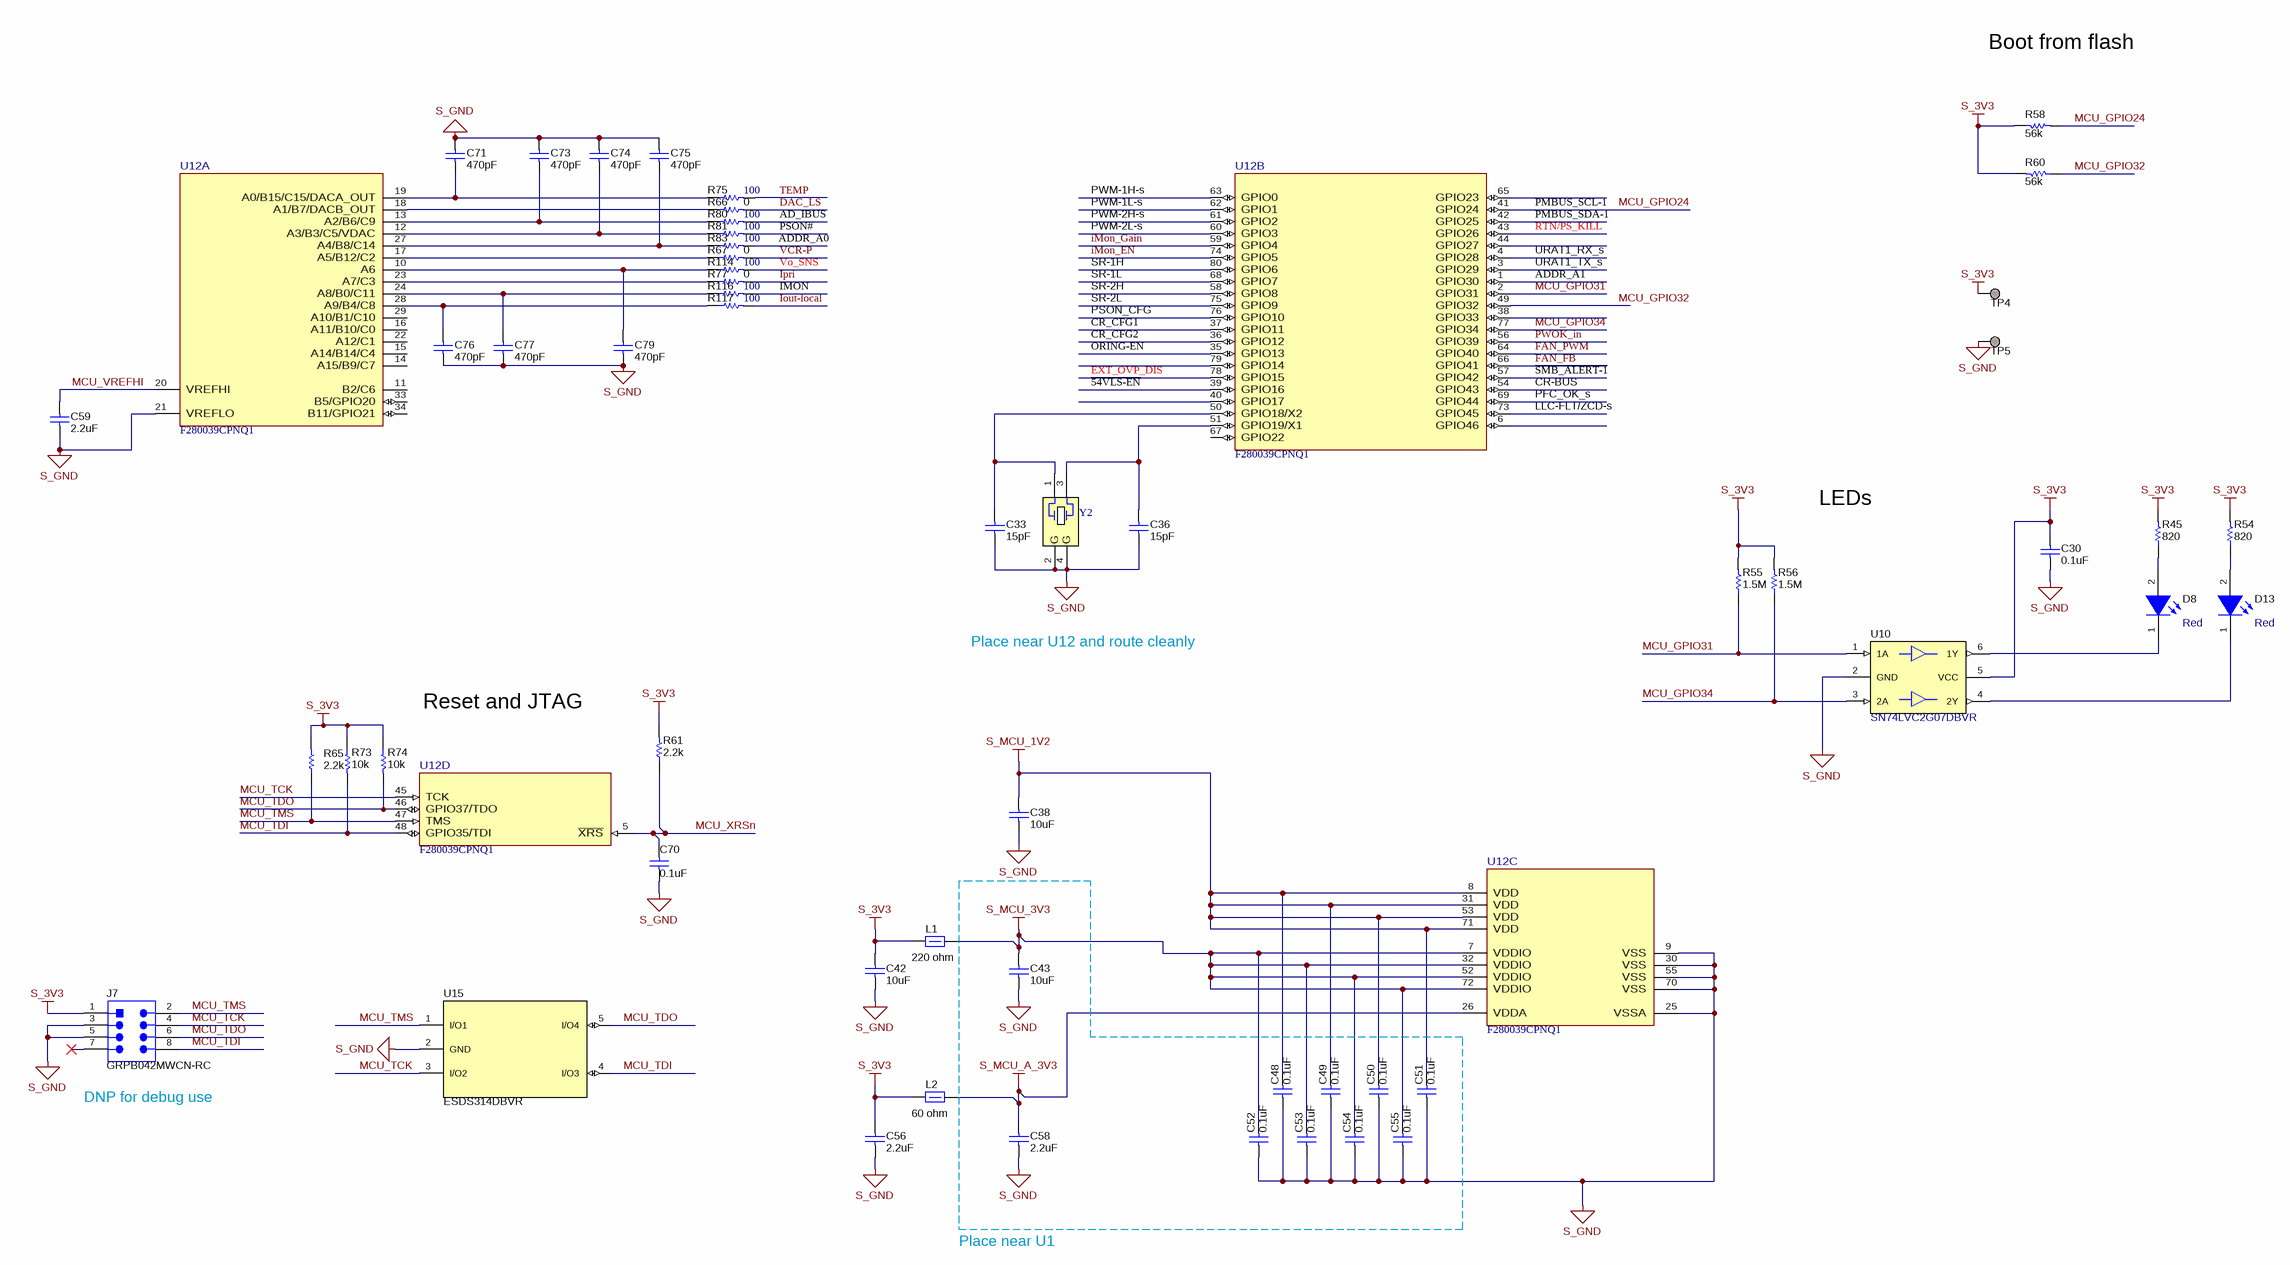
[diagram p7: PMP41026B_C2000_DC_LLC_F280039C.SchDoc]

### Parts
C30  ValueDisplayed: 0.1uF  [0402]  (hidden comment: 885012105010)
C33  ValueDisplayed: 15pF  [0402]  (hidden comment: 885012005056)
C36  ValueDisplayed: 15pF  [0402]  (hidden comment: 885012005056)
C38  ValueDisplayed: 10uF  [0603]  (hidden comment: GRM188R61A106ME69D)
C42  ValueDisplayed: 10uF  [0805_HV]  (hidden comment: LMK212ABJ106KG-T)
C43  ValueDisplayed: 10uF  [0603]  (hidden comment: GRM188R61A106ME69D)
C48  ValueDisplayed: 0.1uF  [0402]  (hidden comment: 885012105010)
C49  ValueDisplayed: 0.1uF  [0402]  (hidden comment: 885012105010)
C50  ValueDisplayed: 0.1uF  [0402]  (hidden comment: 885012105010)
C51  ValueDisplayed: 0.1uF  [0402]  (hidden comment: 885012105010)
C52  ValueDisplayed: 0.1uF  [0402]  (hidden comment: 885012105010)
C53  ValueDisplayed: 0.1uF  [0402]  (hidden comment: 885012105010)
C54  ValueDisplayed: 0.1uF  [0402]  (hidden comment: 885012105010)
C55  ValueDisplayed: 0.1uF  [0402]  (hidden comment: 885012105010)
C56  ValueDisplayed: 2.2uF  [0603]  (hidden comment: CGA3E3X5R1A225K080AB)
C58  ValueDisplayed: 2.2uF  [0603]  (hidden comment: CGA3E3X5R1A225K080AB)
C59  ValueDisplayed: 2.2uF  [0603]  (hidden comment: CGA3E3X5R1A225K080AB)
C70  ValueDisplayed: 0.1uF  [0402]  (hidden comment: 885012105010)
C71  ValueDisplayed: 470pF  [0402]  (hidden comment: CGA2B2X7R1H471K050BA)
C73  ValueDisplayed: 470pF  [0402]  (hidden comment: CGA2B2X7R1H471K050BA)
C74  ValueDisplayed: 470pF  [0402]  (hidden comment: CGA2B2X7R1H471K050BA)
C75  ValueDisplayed: 470pF  [0402]  (hidden comment: CGA2B2X7R1H471K050BA)
C76  ValueDisplayed: 470pF  [0402]  (hidden comment: CGA2B2X7R1H471K050BA)
C77  ValueDisplayed: 470pF  [0402]  (hidden comment: CGA2B2X7R1H471K050BA)
C79  ValueDisplayed: 470pF  [0402]  (hidden comment: CGA2B2X7R1H471K050BA)
D8  value Red  [WL-SMCW_RED_0805]  (hidden comment: 150080SS75000)
D13  value Red  [WL-SMCW_RED_0805]  (hidden comment: 150080SS75000)
J7  GRPB042MWCN-RC  [Sullins_GRPB042MWCN]
L1  value 220 ohm  [0805_HV]  (hidden comment: BLM21PG221SN1D)
L2  value 60 ohm  [0805_HV]  (hidden comment: 742792063)
R45  ValueDisplayed: 820  [0402]  (hidden comment: CRCW0402820RJNED)
R54  ValueDisplayed: 820  [0402]  (hidden comment: CRCW0402820RJNED)
R55  ValueDisplayed: 1.5M  [0402]  (hidden comment: CRCW04021M50JNED)
R56  ValueDisplayed: 1.5M  [0402]  (hidden comment: CRCW04021M50JNED)
R58  ValueDisplayed: 56k  [0402]  (hidden comment: CRCW040256K0JNED)
R60  ValueDisplayed: 56k  [0402]  (hidden comment: CRCW040256K0JNED)
R61  ValueDisplayed: 2.2k  [0402]  (hidden comment: CRCW04022K20JNED)
R65  ValueDisplayed: 2.2k  [0402]  (hidden comment: CRCW04022K20JNED)
R66  ValueDisplayed: 0  [0402]  (hidden comment: CRCW04020000Z0ED)
R67  ValueDisplayed: 0  [0402]  (hidden comment: CRCW04020000Z0ED)
R73  ValueDisplayed: 10k  [0402]  (hidden comment: CRCW040210K0JNED)
R74  ValueDisplayed: 10k  [0402]  (hidden comment: CRCW040210K0JNED)
R75  ValueDisplayed: 100  [0402]  (hidden comment: RC0402FR-07100RL)
R77  ValueDisplayed: 0  [0402]  (hidden comment: CRCW04020000Z0ED)
R80  ValueDisplayed: 100  [0402]  (hidden comment: RC0402FR-07100RL)
R81  ValueDisplayed: 100  [0402]  (hidden comment: RC0402FR-07100RL)
R83  ValueDisplayed: 100  [0402]  (hidden comment: RC0402FR-07100RL)
R114  ValueDisplayed: 100  [0402]  (hidden comment: RC0402FR-07100RL)
R116  ValueDisplayed: 100  [0402]  (hidden comment: RC0402FR-07100RL)
R117  ValueDisplayed: 100  [0402]  (hidden comment: RC0402FR-07100RL)
TP4  3V3  [TP_50MIL-25MILHOLE]  (value not drawn)  (no BOM)
TP5  GND  [TP_50MIL-25MILHOLE]  (value not drawn)  (no BOM)
U10  SN74LVC2G07DBVR  [DBV0006A_N]
U12  F280039CPNQ1  [PN0080A-MFG]  (parts A,B,C,D of 4)
U15  ESDS314DBVR  [DBV0005A_N]
Y2  ECS-200-18-30B-AGN-TR  [ECS_ECX-53B]  (value not drawn)

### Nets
S_3V3: C30.1 C42.2 C56.2 J7.1 L1.1 L2.1 R45.2 R54.2 R55.2 R56.2 R58.1 R60.2 R61.2 R65.2 R73.1 R74.1 TP4.1 U10.5(VCC)
S_GND: C30.2 C33.2 C36.2 C38.1 C42.1 C43.2 C48.2 C49.2 C50.2 C51.2 C52.2 C53.2 C54.2 C55.2 C56.1 C58.1 C59.1 C70.2 C71.1 C73.1 C74.1 C75.1 C76.2 C77.2 C79.2 J7.3 J7.5 TP5.1 U10.2(GND) U12.9(VSS) U12.21(VREFLO) U12.25(VSSA) U12.30(VSS) U12.55(VSS) U12.70(VSS) U15.2(GND) Y2.2(GND) Y2.4(GND)  [project net S_AGND]
S_MCU_1V2: C38.2 C48.1 C49.1 C50.1 C51.1 U12.8(VDD) U12.31(VDD) U12.53(VDD) U12.71(VDD)
S_MCU_3V3: C43.1 C52.1 C53.1 C54.1 C55.1 L1.2 U12.7(VDDIO) U12.32(VDDIO) U12.52(VDDIO) U12.72(VDDIO)
S_MCU_A_3V3: C58.2 L2.2 U12.26(VDDA)
~{54VLS-EN}: U12.39(GPIO16)
~{SMB_ALERT-1}: U12.57(GPIO42)
AD_IBUS: R80.2
ADDR_A0: R83.2
ADDR_A1: U12.1(GPIO30)
CR-BUS: U12.54(GPIO43)
CR_CFG1: U12.37(GPIO11)
CR_CFG2: U12.36(GPIO12)
DAC_LS: R66.2
EXT_OVP_DIS: U12.78(GPIO15)
FAN_FB: U12.66(GPIO41)
FAN_PWM: U12.64(GPIO40)
IMON: R116.2
iMon_EN: U12.74(GPIO5)
iMon_Gain: U12.59(GPIO4)
Iout-local: R117.2
Ipri: R77.2
LLC-FLT/ZCD-s: U12.73(GPIO45)
MCU_GPIO24: R58.2 U12.41(GPIO24)  [also labelled PMBUS_SCL-1]
MCU_GPIO31: R55.1 U10.1(1A) U12.2(GPIO31)
MCU_GPIO32: R60.1 U12.49(GPIO32)
MCU_GPIO34: R56.1 U10.3(2A) U12.77(GPIO34)
MCU_TCK: J7.4 U12.45(TCK) U15.3(I/O2)
MCU_TDI: J7.8 R73.2 U12.48(GPIO35/TDI) U15.4(I/O3)
MCU_TDO: J7.6 R74.2 U12.46(GPIO37/TDO) U15.5(I/O4)
MCU_TMS: J7.2 R65.1 U12.47(TMS) U15.1(I/O1)
MCU_VREFHI: C59.2 U12.20(VREFHI)
MCU_XRSn: C70.1 R61.1 U12.5(~{XRS})
ORING-EN: U12.35(GPIO13)
PFC_OK_s: U12.69(GPIO44)
PMBUS_SDA-1: U12.42(GPIO25)
PSON#: R81.2
PSON_CFG: U12.76(GPIO10)
PWM-1H-s: U12.63(GPIO0)
PWM-1L-s: U12.62(GPIO1)
PWM-2H-s: U12.61(GPIO2)
PWM-2L-s: U12.60(GPIO3)
PWOK_in: U12.56(GPIO39)
RTN/PS_KILL: U12.43(GPIO26)
SR-1H: U12.80(GPIO6)
SR-1L: U12.68(GPIO7)
SR-2H: U12.58(GPIO8)
SR-2L: U12.75(GPIO9)
TEMP: R75.2
URAT1_RX_s: U12.4(GPIO28)
URAT1_TX_s: U12.3(GPIO29)
VCR-P: R67.2
Vo_SNS: R114.2
NetC33_1: C33.1 U12.50(GPIO18/X2) Y2.1
NetC36_1: C36.1 U12.51(GPIO19/X1) Y2.3
NetC71_2: C71.2 R75.1 U12.19(A0/B15/C15/DACA_OUT)
NetC73_2: C73.2 R80.1 U12.13(A2/B6/C9)
NetC74_2: C74.2 R81.1 U12.12(A3/B3/C5/VDAC)
NetC75_2: C75.2 R83.1 U12.27(A4/B8/C14)
NetC76_1: C76.1 R117.1 U12.28(A9/B4/C8)
NetC77_1: C77.1 R116.1 U12.24(A8/B0/C11)
NetC79_1: C79.1 R114.1 U12.10(A6)
NetD8_1: D8.1(K) U10.6(1Y)
NetD8_2: D8.2(A) R45.1
NetD13_1: D13.1(K) U10.4(2Y)
NetD13_2: D13.2(A) R54.1
NetR66_1: R66.1 U12.18(A1/B7/DACB_OUT)
NetR67_1: R67.1 U12.17(A5/B12/C2)
NetR77_1: R77.1 U12.23(A7/C3)

Not connected (* = marked no-connect by the designer): J7 7*; U12 6(GPIO46) 11(B2/C6) 14(A15/B9/C7) 15(A14/B14/C4) 16(A11/B10/C0) 22(A12/C1) 29(A10/B1/C10) 33(B5/GPIO20) 34(B11/GPIO21) 38(GPIO33) 40(GPIO17) 44(GPIO27) 65(GPIO23) 67(GPIO22) 79(GPIO14)

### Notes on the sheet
- Boot from flash
- LEDs
- Place near U12 and route cleanly
- Reset and JTAG
- (near J7) DNP for debug use
- Place near U1

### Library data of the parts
C30 = CMP-0006221-2: CAP, CERM, 0.1 uF, 10 V, +/- 20%, X5R, 0402; Manufacturer: Wurth Elektronik; Polarized: N; Value: 0.1uF; U/M: EA; Cap_F: 100nF; Value1: Unknown; VDC_V: 10V; TaMin_C: -55°C; TaMax_C: 85°C; AEC Category: Q200; SizeArea_mm2: 0.5; SizeAreaWB_mm2: 3; SizeX_mm: 1; SizeZ_mm: 0.6
C33 C36 = CMP-0006216-2: CAP, CERM, 15 pF, 50 V, +/- 5%, C0G/NP0, 0402; Manufacturer: Wurth Elektronik; Polarized: N; Value: 15pF; U/M: EA; Value1: Unknown; VDC_V: 50V; TaMin_C: -55°C; TaMax_C: 125°C; AEC Category: Q200; SizeArea_mm2: 0.5; SizeAreaWB_mm2: 3; SizeX_mm: 1; SizeZ_mm: 0.6
C38 C43 = CMP-0007318-5: CAP, CERM, 10 uF, 10 V, +/- 20%, X5R, 0603; Manufacturer: MuRata; Polarized: N; Value: 10uF; U/M: EA; Cap_F: 10µF; Value1: Unknown; VDC_V: 10V; TaMin_C: -55°C; TaMax_C: 85°C; AEC Category: Q200; SizeArea_mm2: 1.28; SizeAreaWB_mm2: 4.68; SizeX_mm: 1.6; SizeY_mm: 0.8; SizeZ_mm: 1
C42 = CMP-0008395-2: CAP, CERM, 10 uF, 10 V, +/- 10%, X5R, 0805; Manufacturer: Taiyo Yuden; Polarized: N; Value: 10uF; U/M: EA; Cap_F: 10µF; Value1: Unknown; VDC_V: 10V; TaMin_C: -55°C; TaMax_C: 85°C; Cap_Case: 0805; AEC Category: Q200; SizeArea_mm2: 2.5; SizeAreaWB_mm2: 6.75; SizeX_mm: 2; SizeY_mm: 1.25; SizeZ_mm: 1.45
C48-C55 C70 = CMP-0006221-2: CAP, CERM, 0.1 uF, 10 V, +/- 20%, X5R, 0402; Manufacturer: Wurth Elektronik; Polarized: N; Value: 0.1uF; U/M: EA; Cap_F: 100nF; Value1: Unknown; VDC_V: 10V; TaMin_C: -55°C; TaMax_C: 85°C; SizeArea_mm2: 0.5; SizeAreaWB_mm2: 3; SizeX_mm: 1; SizeZ_mm: 0.6; AEC Category: Q200
C56 C58 C59 = CMP-0007091-5: CAP, CERM, 2.2 uF, 10 V, +/- 10%, X5R, AEC-Q200 Grade 3, 0603; Manufacturer: TDK; Polarized: N; Value: 2.2uF; U/M: EA; Cap_F: 2.2µF; Value1: Unknown; VDC_V: 10V; TaMin_C: -55°C; TaMax_C: 85°C; AEC Category: Q200; AEC Qualified: Y; AEC Grade: 3; SizeArea_mm2: 1.28; SizeAreaWB_mm2: 4.68; SizeX_mm: 1.6; SizeY_mm: 0.8; SizeZ_mm: 1
C71 C73-C77 C79 = CMP-0006320-2: CAP, CERM, 470 pF, 50 V, +/- 10%, X7R, AEC-Q200 Grade 1, 0402; Manufacturer: TDK; TaMin_C: -55°C; ESR_ohm: 4.96489; Polarized: N; SizeAreaWB_mm2: 3; Value1: 4.96489 ohm; U/M: EA; Value: 470pF; TaMax_C: 125°C; SizeZ_mm: 0.6; SizeX_mm: 1; SizeY_mm: 0.5; Value2: 50V; CompType: Capacitor; AEC Qualified: Y; IRMS_A: 2.28414dA; AEC Category: Q200
D8 D13 = CMP-0002951-3: LED, Red, SMD; Manufacturer: Wurth Elektronik; Type: AlInGaP; Vf_V: 1.9V; Io_A: 30mA; Vr_V: 5V; Ir_A: 25µA; Tjmax_C: 85°C; Power_TotalModule: 72mW; Value1: 0.072W; Angle: 140
J7 = CMP-0086278-1: Header, 1.27mm, 4x2, Gold, R/A, TH; Manufacturer: Sullins Connector Solutions; Current_A: 1A; Shrouded: N; Pitch_mm: 1.27; Voltage_V: 500V; Gender: Male; Row_Count: 2
L1 = CMP-0003363-1: Ferrite Bead, 220 ohm @ 100 MHz, 2 A, 0805; Manufacturer: MuRata; Imax_A: 2A; DCR_ohm: 0.045; Value1: 0.045 ohm; ZTyp@100MHz_Ohm: 220; SizeArea_mm2: 2.5; SizeAreaWB_mm2: 6.75; SizeX_mm: 2; SizeY_mm: 1.25; SizeZ_mm: 1.45
L2 = CMP-0003093-1: Ferrite Bead, 60 ohm @ 100 MHz, 3 A, 0805; Manufacturer: Wurth Elektronik; Ztyp@1GHz_Ohm: 95.384; ZTyp@100MHz_Ohm: 60; SizeAreaWB_mm2: 6.75; DCR_ohm: 0.025; Value1: 0.025 ohm; Imax_A: 3A; SizeZ_mm: 1.45; SizeX_mm: 2; SizeY_mm: 1.25; SizeArea_mm2: 2.5
R45 R54 = CMP-0026979-3: RES, 820, 5%, 0.063 W, AEC-Q200 Grade 0, 0402; Manufacturer: Vishay-Dale; Power_W: 63mW; TempCo: 200 ppm/C; Value_Code: 820R; Value: 820; EIA_Code: E24; SizeX_mm: 1; SizeY_mm: 0.5; SizeZ_mm: 0.6; Value2: 0.063W; AEC Qualified: Y; VDC_V: 50V; AEC Category: Q200; AEC Grade: 0
R55 R56 = CMP-0026863-2: RES, 1.5 M, 5%, 0.063 W, AEC-Q200 Grade 0, 0402; Manufacturer: Vishay-Dale; Power_W: 63mW; TempCo: 200 ppm/C; Value_Code: 1M50; Value: 1.5Meg; EIA_Code: E24; SizeX_mm: 1; SizeY_mm: 0.5; SizeZ_mm: 0.6; Value2: 0.063W; AEC Qualified: Y; VDC_V: 50V; AEC Category: Q200; AEC Grade: 0
R58 R60 = CMP-0026949-3: RES, 56 k, 5%, 0.063 W, AEC-Q200 Grade 0, 0402; Manufacturer: Vishay-Dale; Value: 56k; Value_Code: 56k0; Power_W: 63mW; Value2: 0.063W; VDC_V: 50V; TempCo: 200 ppm/C; EIA_Code: E24; AEC Category: Q200; AEC Qualified: Y; AEC Grade: 0; SizeArea_mm2: 0.5; SizeX_mm: 1; SizeZ_mm: 0.6
R61 R65 = CMP-0026890-5: RES, 2.2 k, 5%, 0.063 W, AEC-Q200 Grade 0, 0402; Manufacturer: Vishay-Dale; Value: 2.2k; Value_Code: 2k20; Power_W: 63mW; Value2: 0.063W; VDC_V: 50V; TempCo: 200 ppm/C; EIA_Code: E24; AEC Category: Q200; AEC Qualified: Y; AEC Grade: 0; SizeArea_mm2: 0.5; SizeX_mm: 1; SizeZ_mm: 0.6
R66 R67 R77 = CMP-0026822-3: RES, 0, 5%, 0.063 W, AEC-Q200 Grade 0, 0402; Manufacturer: Vishay-Dale; Power_W: 63mW; TempCo: 200 ppm/C; Value_Code: 0000; Value: 0; EIA_Code: E24; SizeX_mm: 1; SizeY_mm: 0.5; SizeZ_mm: 0.6; Value2: 0.063W; AEC Qualified: Y; VDC_V: 50V; AEC Category: Q200
R73 R74 = CMP-0026825-5: as R90-R93 on sheet PMP41026B_C2000_DC_LLC_Control
R75 R80 R81 R83 R114 R116 R117 = CMP-0026722-1: as R46 on sheet PMP41026B_C2000_DC_LLC_Control
TP4 TP5 = CMP-0078143-3: TEST POINT.  No entry in BOM.
U10 = CMP-0051789-2: Dual Buffer/Driver with Open-Drain Output, DBV0006A, LARGE T&R; Manufacturer: Texas Instruments; 3-State Output: No; Bits(#): 2; F @ Nom Voltage(Max)(Mhz): 150; ICC @ Nom Voltage(Max)(mA): 0.01; Input Type: CMOS/TTL; Logic: True; Output Drive (IOL/IOH)(Max)(mA): 32/-32; Output Type: CMOS; Rating: Catalog; Sub-Family: Inverting Buffer/Driver; Technology Family: LVC; tpd @ Nom Voltage(Max)(ns): 8.6,4.4,3.7,2.9; VCC(Max)(V): 5.5; VCC(Min)(V): 1.65; Voltage(Nom)(V): 1.8,2.5,3.3,5; AEC Category: Q200; AEC Qualified: N; CompType: IC; Green_Lifecycle: Active; Green_REACh: Passed; SizeArea_mm2: 8.12; SizeAreaWB_mm2: 14.82; SizeX_mm: 2.8; SizeY_mm: 2.9; SizeZ_mm: 1.45
U12 = CMP-0121731-1: Automotive C2000™ 32-bit MCU 120-MHz 384-KB flash, FPU, TMU with CLA, CLB, AES and CAN-FD 80-LQFP -40 to 125; Manufacturer: Texas Instruments; SizeZ_mm: 1.6mm; AEC Qualified: Yes; AEC Grade: Grade 1; Core Architecture: C28x; Data Bus Width: 32bits; Frequency_Fixed: 120MHz; Interface: I2C,SPI,UART,CAN,LIN,SCI; Max Supply Voltage: 3.63V; Memory Size: 384KBytes; Min Supply Voltage: 1.14V; Number Of A/D Converters: 3; Number Of Adc Channels: 18; Number Of Cores: 1; Number Of I/Os: 39; Number Of I2C Channels: 2; Number Of Pwm Channels: 16; Number Of Uart Channels: 4; Ram Size: 69KBytes; Standoff Height: 0.05mm; TaMax_C: +125°C; TaMin_C: -40°C; TJmax_C: +150°C
U15 = CMP-0085635-1: Data-Line Surge and ESD Protection Diode Array, DBV0005A (SOT-23-5); Alternate Manufacturer: Texas Instruments; CompType: IC; SizeX_mm: 2.8; Rating: Catalog; AEC Category: Q200; SizeZ_mm: 1.45; SizeArea_mm2: 8.12; AEC Qualified: N; SizeAreaWB_mm2: 14.82; SizeY_mm: 2.9
Y2 = CMP-0080365-2: Crystal, 20 MHz, 25 ppm, 18 pF, SMD; Manufacturer: ECS Inc.; Frequency Stability: 30 ppm; AEC Qualified: N; Frequency Tolerance: 25 ppm; AEC Category: Q200; TaMax_C: 85°C; Frequency_Fixed: 20MHz; TaMin_C: -40°C; Load Capacitance: 18 pF

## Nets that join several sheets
3V3: PMP41026B_C2000_DC_PFC_1 (8 pins), PMP41026B_C2000_DC_PFC_2 (9 pins)
3V3A: PMP41026B_C2000_DC_PFC_1 (13 pins), PMP41026B_C2000_DC_PFC_2 (C24.2 CP4.2 LP2.2 U1.18)
5Vp: PMP41026B_C2000_DC_PFC_1 (C16.1 J21.1 J22.2 U5.1), PMP41026B_C2000_DC_PFC_2 (C23.1 U6.1 U6.3)
MCU_1V2: PMP41026B_C2000_DC_PFC_1 (R31.2), PMP41026B_C2000_DC_PFC_2 (6 pins)
PGND: PMP41026B_C2000_DC_PFC_1 (55 pins), PMP41026B_C2000_DC_PFC_2 (23 pins)
S_3V3: PMP41026B_C2000_DC_PFC_2 (C28.2 U7.16), PMP41026B_C2000_DC_LLC_Control (17 pins), PMP41026B_C2000_DC_LLC_F280039C (18 pins)
S_AGND: PMP41026B_C2000_DC_PFC_2 (C28.1 U7.9 U7.10), PMP41026B_C2000_DC_LLC_Control (57 pins), PMP41026B_C2000_DC_LLC_F280039C (38 pins)
~{54VLS-EN}: PMP41026B_C2000_DC_LLC_Control (Q5.5 R98.1), PMP41026B_C2000_DC_LLC_F280039C (U12.39)
~{SMB_ALERT-1}: PMP41026B_C2000_DC_LLC_Control (Q6.2 R88.2), PMP41026B_C2000_DC_LLC_F280039C (U12.57)
AD_IBUS: PMP41026B_C2000_DC_LLC_Control (R76.2 R99.1), PMP41026B_C2000_DC_LLC_F280039C (R80.2)
ADDR_A0: PMP41026B_C2000_DC_LLC_Control (J6.3), PMP41026B_C2000_DC_LLC_F280039C (R83.2)
ADDR_A1: PMP41026B_C2000_DC_LLC_Control (J4.14), PMP41026B_C2000_DC_LLC_F280039C (U12.1)
Bulk_OK: PMP41026B_C2000_DC_PFC_1 (U1.47), PMP41026B_C2000_DC_PFC_2 (U7.2)
CR-BUS: PMP41026B_C2000_DC_LLC_Control (J4.12 Q9.3 Q10.3 R44.2), PMP41026B_C2000_DC_LLC_F280039C (U12.54)
CR_CFG1: PMP41026B_C2000_DC_LLC_Control (Q9.1), PMP41026B_C2000_DC_LLC_F280039C (U12.37)
CR_CFG2: PMP41026B_C2000_DC_LLC_Control (Q10.1), PMP41026B_C2000_DC_LLC_F280039C (U12.36)
DAC_LS: PMP41026B_C2000_DC_LLC_Control (R100.1), PMP41026B_C2000_DC_LLC_F280039C (R66.2)
FAN_FB: PMP41026B_C2000_DC_LLC_Control (R107.1), PMP41026B_C2000_DC_LLC_F280039C (U12.66)
FAN_PWM: PMP41026B_C2000_DC_LLC_Control (R112.2), PMP41026B_C2000_DC_LLC_F280039C (U12.64)
IMON: PMP41026B_C2000_DC_LLC_Control (J6.5), PMP41026B_C2000_DC_LLC_F280039C (R116.2)
iMon_EN: PMP41026B_C2000_DC_LLC_Control (J4.16), PMP41026B_C2000_DC_LLC_F280039C (U12.74)
iMon_Gain: PMP41026B_C2000_DC_LLC_Control (J4.18), PMP41026B_C2000_DC_LLC_F280039C (U12.59)
Input_OK: PMP41026B_C2000_DC_PFC_1 (U1.38), PMP41026B_C2000_DC_PFC_2 (U7.3)
Iout-local: PMP41026B_C2000_DC_LLC_Control (J6.13), PMP41026B_C2000_DC_LLC_F280039C (R117.2)
Ipri: PMP41026B_C2000_DC_LLC_Control (C31.1 R46.2 R50.2), PMP41026B_C2000_DC_LLC_F280039C (R77.2)
LLC-FLT/ZCD-s: PMP41026B_C2000_DC_LLC_Control (J4.13), PMP41026B_C2000_DC_LLC_F280039C (U12.73)
MCU_GPIO24: PMP41026B_C2000_DC_LLC_Control (R109.1), PMP41026B_C2000_DC_LLC_F280039C (R58.2 U12.41)
ORING-EN: PMP41026B_C2000_DC_LLC_Control (J4.20), PMP41026B_C2000_DC_LLC_F280039C (U12.35)
PFC_OK_s: PMP41026B_C2000_DC_PFC_2 (U7.15), PMP41026B_C2000_DC_LLC_F280039C (U12.69)
PMBUS_SDA-1: PMP41026B_C2000_DC_LLC_Control (R108.1), PMP41026B_C2000_DC_LLC_F280039C (U12.42)
PSON#: PMP41026B_C2000_DC_LLC_Control (C57.1 J4.15 R82.1 R85.2), PMP41026B_C2000_DC_LLC_F280039C (R81.2)
PSON_CFG: PMP41026B_C2000_DC_LLC_Control (Q6.5), PMP41026B_C2000_DC_LLC_F280039C (U12.76)
PWM-1H-s: PMP41026B_C2000_DC_LLC_Control (J4.5), PMP41026B_C2000_DC_LLC_F280039C (U12.63)
PWM-1L-s: PMP41026B_C2000_DC_LLC_Control (J4.7), PMP41026B_C2000_DC_LLC_F280039C (U12.62)
PWM-2H-s: PMP41026B_C2000_DC_LLC_Control (J4.4), PMP41026B_C2000_DC_LLC_F280039C (U12.61)
PWM-2L-s: PMP41026B_C2000_DC_LLC_Control (J4.6), PMP41026B_C2000_DC_LLC_F280039C (U12.60)
PWOK_in: PMP41026B_C2000_DC_LLC_Control (D9.2 Q7.1 R92.2 R93.2), PMP41026B_C2000_DC_LLC_F280039C (U12.56)
RTN/PS_KILL: PMP41026B_C2000_DC_LLC_Control (J6.10 R49.2 R51.1), PMP41026B_C2000_DC_LLC_F280039C (U12.43)
SCI_RX0: PMP41026B_C2000_DC_PFC_1 (U1.2), PMP41026B_C2000_DC_PFC_2 (U7.6)
SCI_TX0: PMP41026B_C2000_DC_PFC_1 (U1.1), PMP41026B_C2000_DC_PFC_2 (U7.5)
SR-1H: PMP41026B_C2000_DC_LLC_Control (J4.9), PMP41026B_C2000_DC_LLC_F280039C (U12.80)
SR-1L: PMP41026B_C2000_DC_LLC_Control (J4.11), PMP41026B_C2000_DC_LLC_F280039C (U12.68)
SR-2H: PMP41026B_C2000_DC_LLC_Control (J4.8), PMP41026B_C2000_DC_LLC_F280039C (U12.58)
SR-2L: PMP41026B_C2000_DC_LLC_Control (J4.10), PMP41026B_C2000_DC_LLC_F280039C (U12.75)
SYNC/PLL: PMP41026B_C2000_DC_PFC_1 (U1.43), PMP41026B_C2000_DC_PFC_2 (U7.4)
TCK: PMP41026B_C2000_DC_PFC_1 (R29.2 U1.28), PMP41026B_C2000_DC_PFC_2 (J3.4 U8.3)
TDI: PMP41026B_C2000_DC_PFC_1 (R38.1 U1.31), PMP41026B_C2000_DC_PFC_2 (J3.8 U8.5)
TDO: PMP41026B_C2000_DC_PFC_1 (R30.2 U1.29), PMP41026B_C2000_DC_PFC_2 (J3.6 U8.1)
TEMP: PMP41026B_C2000_DC_LLC_Control (C61.1 U16.3), PMP41026B_C2000_DC_LLC_F280039C (R75.2)
TMS: PMP41026B_C2000_DC_PFC_1 (R37.2 U1.30), PMP41026B_C2000_DC_PFC_2 (J3.2 U8.4)
URAT1_RX_s: PMP41026B_C2000_DC_PFC_2 (U7.12), PMP41026B_C2000_DC_LLC_F280039C (U12.4)
URAT1_TX_s: PMP41026B_C2000_DC_PFC_2 (U7.11), PMP41026B_C2000_DC_LLC_F280039C (U12.3)
VCR-P: PMP41026B_C2000_DC_LLC_Control (C40.1 R64.2), PMP41026B_C2000_DC_LLC_F280039C (R67.2)
VINOK-s: PMP41026B_C2000_DC_PFC_2 (U7.14), PMP41026B_C2000_DC_LLC_Control (R113.1)
Vo_SNS: PMP41026B_C2000_DC_LLC_Control (C29.2 R47.2 U9.1), PMP41026B_C2000_DC_LLC_F280039C (R114.2)

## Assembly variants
001: not fitted C35 C44 C47 FID1 FID2 FID3 R46 R48 R52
